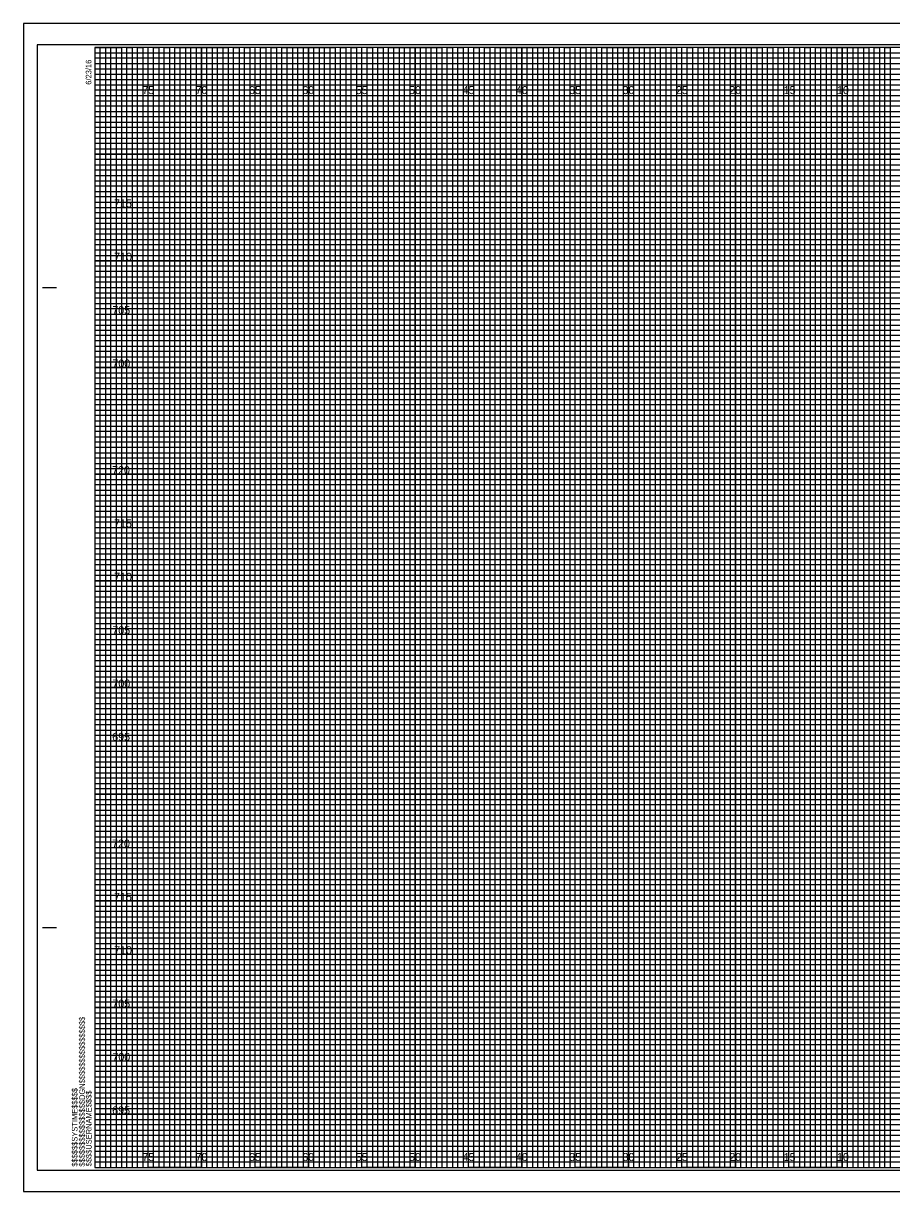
# Model space of a CAD drawing. Extents: x -7 to 162, y -2 to 107.
# Drawn here: x -6.7 to 74.6, y -2.2 to 107.2 of the extents above; entities that cross this region are included whole.
import ezdxf

# ---------------------------------------------------------------- set-up
doc = ezdxf.new("R2010")
doc.units = 0
for name, color, linetype in [('Exist Cross Section Cell', 7, 'Continuous'), ('Exist XS Center Line Elevation Label', 7, 'Continuous'), ('Exist XS Ground Line', 7, 'Continuous'), ('Prop CMT Pvmt Course 2', 7, 'Continuous'), ('Prop CMT Pvmt Course 3', 7, 'Continuous'), ('Prop CMT Pvmt Surface', 7, 'Continuous'), ('Prop CMT Pvmt Surface Shoulder', 7, 'Continuous'), ('Prop CMT Shld Paved Course 1', 7, 'Continuous'), ('Prop CMT Shld Paved Course 2', 7, 'Continuous'), ('Prop CMT Subgrade Earthwork', 7, 'Continuous'), ('Scratch_Level_7', 7, 'Continuous')]:
    doc.layers.add(name, color=color, linetype=linetype)

msp = doc.modelspace()

# ---------------------------------------------------------------- linework, layer by layer
at = {"layer": 'Exist XS Center Line Elevation Label'}
for points in [[(0, 105), (2.5, 105), (2.5, 0), (7.5, 0), (7.5, 105), (12.5, 105), (12.5, 0), (17.5, 0), (17.5, 105), (22.5, 105), (22.5, 0), (27.5, 0), (27.5, 105), (32.5, 105), (32.5, 0), (37.5, 0), (37.5, 105), (42.5, 105), (42.5, 0), (47.5, 0), (47.5, 105), (52.5, 105), (52.5, 0), (57.5, 0), (57.5, 105), (62.5, 105), (62.5, 0), (67.5, 0), (67.5, 105), (72.5, 105), (72.5, 0), (77.5, 0)], [(0, 102.5), (137.5, 102.5)], [(0, 92.5), (160, 92.5), (160, 97.5), (0, 97.5)], [(0, 82.5), (160, 82.5), (160, 87.5), (0, 87.5)], [(0, 72.5), (160, 72.5), (160, 77.5), (0, 77.5)], [(0, 62.5), (160, 62.5), (160, 67.5), (0, 67.5)], [(0, 52.5), (160, 52.5), (160, 57.5), (0, 57.5)], [(0, 42.5), (160, 42.5), (160, 47.5), (0, 47.5)], [(0, 32.5), (160, 32.5), (160, 37.5), (0, 37.5)], [(0, 22.5), (160, 22.5), (160, 27.5), (0, 27.5)], [(0, 12.5), (160, 12.5), (160, 17.5), (0, 17.5)], [(0, 2.5), (160, 2.5), (160, 7.5), (0, 7.5)]]:
    msp.add_lwpolyline(points, dxfattribs=at)
at = {"layer": 'Exist XS Ground Line'}
for p, q in [((5, 105), (0, 105)), ((5, 0), (5, 105)), ((15, 105), (10, 105)), ((10, 105), (10, 0)), ((15, 0), (15, 105)), ((25, 105), (20, 105)), ((20, 105), (20, 0)), ((25, 0), (25, 105)), ((35, 105), (30, 105)), ((30, 105), (30, 0)), ((35, 0), (35, 105)), ((45, 105), (40, 105)), ((40, 105), (40, 0)), ((45, 0), (45, 105)), ((55, 105), (50, 105)), ((50, 105), (50, 0)), ((55, 0), (55, 105)), ((65, 105), (60, 105)), ((60, 105), (60, 0)), ((65, 0), (65, 105)), ((75, 105), (70, 105)), ((70, 105), (70, 0)), ((10, 0), (5, 0)), ((20, 0), (15, 0)), ((30, 0), (25, 0)), ((40, 0), (35, 0)), ((50, 0), (45, 0)), ((60, 0), (55, 0)), ((70, 0), (65, 0))]:
    msp.add_line(p, q, dxfattribs=at)
for points in [[(0, 100), (160, 100), (160, 95), (0, 95)], [(0, 90), (160, 90), (160, 85), (0, 85)], [(0, 80), (160, 80), (160, 75), (0, 75)], [(0, 70), (160, 70), (160, 65), (0, 65)], [(0, 60), (160, 60), (160, 55), (0, 55)], [(0, 50), (160, 50), (160, 45), (0, 45)], [(0, 40), (160, 40), (160, 35), (0, 35)], [(0, 30), (160, 30), (160, 25), (0, 25)], [(0, 20), (160, 20), (160, 15), (0, 15)], [(0, 10), (160, 10), (160, 5), (0, 5)]]:
    msp.add_lwpolyline(points, dxfattribs=at)
at = {"layer": 'Prop CMT Pvmt Course 2'}
msp.add_lwpolyline([(-6.7, -2.25), (161.65, -2.25), (161.65, 107.25), (-6.7, 107.25)], close=True, dxfattribs=at)
at = {"layer": 'Prop CMT Pvmt Course 3'}
msp.add_lwpolyline([(-5.4, -0.25), (161.2, -0.25), (161.2, 105.25), (-5.4, 105.25)], close=True, dxfattribs=at)
at = {"layer": 'Prop CMT Pvmt Surface'}
for p, q in [((161.65, 107.25), (-6.7, 107.25)), ((-6.7, 107.25), (-6.7, -2.25)), ((-6.7, -2.25), (161.65, -2.25))]:
    msp.add_line(p, q, dxfattribs=at)
at = {"layer": 'Prop CMT Shld Paved Course 1'}
for p, q in [((-4.9, 82.5), (-3.65, 82.5)), ((-4.85, 82.5), (-3.6, 82.5)), ((-4.9, 22.5), (-3.65, 22.5)), ((-4.85, 22.5), (-3.6, 22.5)), ((0, 0), (0, 0)), ((0, 0), (0, 0)), ((0, 0), (0, 0)), ((0, 0), (0, 0)), ((0, 0), (0, 0)), ((0, 0), (0, 0)), ((0, 0), (0, 0))]:
    msp.add_line(p, q, dxfattribs=at)
msp.add_lwpolyline([(160, 105), (0, 105), (0, 0), (160, 0)], close=True, dxfattribs=at)
at = {"layer": 'Prop CMT Shld Paved Course 2'}
for points in [[(0, 0), (0.5, 0), (0.5, 105), (1, 105), (1, 0)], [(1, 0), (1.5, 0), (1.5, 105), (2, 105), (2, 0)], [(2.5, 0), (3, 0), (3, 105), (3.5, 105), (3.5, 0)], [(3.5, 0), (4, 0), (4, 105), (4.5, 105), (4.5, 0)], [(5, 0), (5.5, 0), (5.5, 105), (6, 105), (6, 0)], [(6, 0), (6.5, 0), (6.5, 105), (7, 105), (7, 0)], [(7.5, 0), (8, 0), (8, 105), (8.5, 105), (8.5, 0)], [(8.5, 0), (9, 0), (9, 105), (9.5, 105), (9.5, 0)], [(10, 0), (10.5, 0), (10.5, 105), (11, 105), (11, 0)], [(11, 0), (11.5, 0), (11.5, 105), (12, 105), (12, 0)], [(12.5, 0), (13, 0), (13, 105), (13.5, 105), (13.5, 0)], [(13.5, 0), (14, 0), (14, 105), (14.5, 105), (14.5, 0)], [(15, 0), (15.5, 0), (15.5, 105), (16, 105), (16, 0)], [(16, 0), (16.5, 0), (16.5, 105), (17, 105), (17, 0)], [(17.5, 0), (18, 0), (18, 105), (18.5, 105), (18.5, 0)], [(18.5, 0), (19, 0), (19, 105), (19.5, 105), (19.5, 0)], [(20, 0), (20.5, 0), (20.5, 105), (21, 105), (21, 0)], [(21, 0), (21.5, 0), (21.5, 105), (22, 105), (22, 0)], [(22.5, 0), (23, 0), (23, 105), (23.5, 105), (23.5, 0)], [(23.5, 0), (24, 0), (24, 105), (24.5, 105), (24.5, 0)], [(25, 0), (25.5, 0), (25.5, 105), (26, 105), (26, 0)], [(26, 0), (26.5, 0), (26.5, 105), (27, 105), (27, 0)], [(27.5, 0), (28, 0), (28, 105), (28.5, 105), (28.5, 0)], [(28.5, 0), (29, 0), (29, 105), (29.5, 105), (29.5, 0)], [(30, 0), (30.5, 0), (30.5, 105), (31, 105), (31, 0)], [(31, 0), (31.5, 0), (31.5, 105), (32, 105), (32, 0)], [(32.5, 0), (33, 0), (33, 105), (33.5, 105), (33.5, 0)], [(33.5, 0), (34, 0), (34, 105), (34.5, 105), (34.5, 0)], [(35, 0), (35.5, 0), (35.5, 105), (36, 105), (36, 0)], [(36, 0), (36.5, 0), (36.5, 105), (37, 105), (37, 0)], [(37.5, 0), (38, 0), (38, 105), (38.5, 105), (38.5, 0)], [(38.5, 0), (39, 0), (39, 105), (39.5, 105), (39.5, 0)], [(40, 0), (40.5, 0), (40.5, 105), (41, 105), (41, 0)], [(41, 0), (41.5, 0), (41.5, 105), (42, 105), (42, 0)], [(42.5, 0), (43, 0), (43, 105), (43.5, 105), (43.5, 0)], [(43.5, 0), (44, 0), (44, 105), (44.5, 105), (44.5, 0)], [(45, 0), (45.5, 0), (45.5, 105), (46, 105), (46, 0)], [(46, 0), (46.5, 0), (46.5, 105), (47, 105), (47, 0)], [(47.5, 0), (48, 0), (48, 105), (48.5, 105), (48.5, 0)], [(48.5, 0), (49, 0), (49, 105), (49.5, 105), (49.5, 0)], [(50, 0), (50.5, 0), (50.5, 105), (51, 105), (51, 0)], [(51, 0), (51.5, 0), (51.5, 105), (52, 105), (52, 0)], [(52.5, 0), (53, 0), (53, 105), (53.5, 105), (53.5, 0)], [(53.5, 0), (54, 0), (54, 105), (54.5, 105), (54.5, 0)], [(55, 0), (55.5, 0), (55.5, 105), (56, 105), (56, 0)], [(56, 0), (56.5, 0), (56.5, 105), (57, 105), (57, 0)], [(57.5, 0), (58, 0), (58, 105), (58.5, 105), (58.5, 0)], [(58.5, 0), (59, 0), (59, 105), (59.5, 105), (59.5, 0)], [(60, 0), (60.5, 0), (60.5, 105), (61, 105), (61, 0)], [(61, 0), (61.5, 0), (61.5, 105), (62, 105), (62, 0)], [(62.5, 0), (63, 0), (63, 105), (63.5, 105), (63.5, 0)], [(63.5, 0), (64, 0), (64, 105), (64.5, 105), (64.5, 0)], [(65, 0), (65.5, 0), (65.5, 105), (66, 105), (66, 0)], [(66, 0), (66.5, 0), (66.5, 105), (67, 105), (67, 0)], [(67.5, 0), (68, 0), (68, 105), (68.5, 105), (68.5, 0)], [(68.5, 0), (69, 0), (69, 105), (69.5, 105), (69.5, 0)], [(70, 0), (70.5, 0), (70.5, 105), (71, 105), (71, 0)], [(71, 0), (71.5, 0), (71.5, 105), (72, 105), (72, 0)], [(72.5, 0), (73, 0), (73, 105), (73.5, 105), (73.5, 0)], [(73.5, 0), (74, 0), (74, 105), (74.5, 105), (74.5, 0)]]:
    msp.add_lwpolyline(points, dxfattribs=at)
at = {"layer": 'Prop CMT Subgrade Earthwork'}
for p, q in [((5, 0), (5, 105)), ((10, 0), (10, 105)), ((15, 0), (15, 105)), ((20, 0), (20, 105)), ((25, 0), (25, 105)), ((30, 0), (30, 105)), ((35, 0), (35, 105)), ((40, 0), (40, 105)), ((45, 0), (45, 105)), ((50, 0), (50, 105)), ((55, 0), (55, 105)), ((60, 0), (60, 105)), ((65, 0), (65, 105)), ((70, 0), (70, 105)), ((0, 100), (160, 100)), ((0, 95), (160, 95)), ((0, 90), (160, 90)), ((0, 85), (160, 85)), ((0, 80), (160, 80)), ((0, 75), (160, 75)), ((0, 70), (160, 70)), ((0, 65), (160, 65)), ((0, 60), (160, 60)), ((0, 55), (160, 55)), ((0, 50), (160, 50)), ((0, 45), (160, 45)), ((0, 40), (160, 40)), ((0, 35), (160, 35)), ((0, 30), (160, 30)), ((0, 25), (160, 25)), ((0, 20), (160, 20)), ((0, 15), (160, 15)), ((0, 10), (160, 10)), ((0, 5), (160, 5))]:
    msp.add_line(p, q, dxfattribs=at)
at = {"layer": 'Scratch_Level_7'}
for p, q in [((0, 104.5), (130, 104.5)), ((130, 103.99), (0, 103.99)), ((0, 103.99), (0, 103.5)), ((0, 103.5), (130, 103.5)), ((130, 102.95), (0, 102.95)), ((0, 102.95), (0, 102)), ((0, 102), (160, 102))]:
    msp.add_line(p, q, dxfattribs=at)
for points in [[(0, 101.5), (135, 101.5), (160, 101.5), (160, 101), (0, 101)], [(0, 100.5), (160, 100.5), (160, 99.5), (0, 99.5)], [(0, 99), (160, 99), (160, 98.5), (0, 98.49)], [(0, 98), (160, 98), (160, 97), (0, 97)], [(0, 96.5), (160, 96.5), (160, 96), (0, 96)], [(0, 95.5), (160, 95.5), (160, 94.5), (0, 94.5)], [(0, 94), (160, 94), (160, 93.5), (0, 93.5)], [(0, 93), (160, 93), (160, 92), (0, 92)], [(0, 91.5), (160, 91.5), (160, 91), (0, 91)], [(0, 90.5), (160, 90.5), (160, 89.5), (0, 89.5)], [(0, 89), (160, 89), (160, 88.5), (0, 88.5)], [(0, 88), (160, 88), (160, 86.98), (160, 86.5), (160, 86), (0, 86)], [(0, 87), (160, 87), (160, 86.5), (0, 86.5)], [(0, 85.5), (160, 85.5), (160, 84.5), (0, 84.52)], [(0, 84.52), (160, 84.5), (160, 84), (0, 84)], [(0, 83.5), (160, 83.5), (160, 83), (0, 83)], [(0, 82), (160, 82), (160, 81.5), (0, 81.5)], [(0, 81), (160, 81), (160, 80.5), (0, 80.5)], [(-0.04, 79.45), (160, 79.45), (160, 78.94), (-0.04, 78.94)], [(0, 78.5), (160, 78.5), (160, 78), (0, 78)], [(0, 77), (160, 77), (160, 76.5), (0, 76.5)], [(0, 76), (160, 76), (160, 75.5), (0, 75.5)], [(0, 74.5), (160, 74.5), (160, 74), (0, 74)], [(0, 73.5), (160, 73.5), (160, 73), (0, 73)], [(0, 72), (160, 72), (160, 71.5), (0, 71.5)], [(0, 71), (160, 71), (160, 70.5), (0, 70.5)], [(0, 69.5), (160, 69.5), (160, 68.99), (0, 69)], [(0, 68.5), (160, 68.5), (160, 68), (0, 68)], [(0, 67), (160, 67), (160, 66.5), (0, 66.5)], [(0, 66), (160, 66), (160, 65.5), (0, 65.5)], [(0, 64.5), (160, 64.5), (160, 64), (0, 64)], [(0, 63.5), (160, 63.5), (160, 63), (0, 63)], [(0, 62), (160, 62), (160, 61.5), (0, 61.5)], [(0, 61), (160, 61), (160, 60.5), (0, 60.5)], [(0, 59.5), (160, 59.5), (160, 59), (0, 59)], [(0, 58.5), (160.03, 58.45), (160, 58), (0, 58)], [(0, 57), (160, 57), (160, 56.5), (0, 56.5)], [(0, 56), (160, 56), (160, 55.5), (0, 55.5)], [(0, 54.5), (160, 54.5), (160, 54), (0, 54)], [(0, 53.5), (160, 53.5), (160, 53), (0, 53)], [(0, 52), (160, 52), (160, 51.5), (0, 51.5)], [(0, 51), (160, 51), (160, 50.5), (0, 50.5)], [(0, 49.5), (160, 49.5), (160, 49), (0, 49)], [(0, 48.5), (160, 48.5), (160, 48), (0, 48)], [(0, 47), (160, 47), (160, 46.5), (0, 46.5)], [(0, 46), (160, 46), (160, 45.5), (0, 45.5)], [(0, 44.5), (160, 44.5), (160, 44), (0, 44)], [(0, 43.5), (160, 43.5), (160, 43), (0, 43)], [(0, 42), (160, 42), (160, 41.5), (0, 41.5)], [(0, 41), (160, 41), (160, 40.5), (0, 40.5)], [(0, 39.5), (160, 39.5), (160, 38.99), (0, 39)], [(0, 38.5), (160, 38.5), (160, 38), (0, 38)], [(0, 37), (160, 37), (160, 36.5), (0, 36.5)], [(0, 36), (160, 36), (160, 35.5), (0, 35.5)], [(0, 34.5), (160, 34.5), (160, 34), (0, 34)], [(0, 33.5), (160, 33.5), (160, 33), (0, 33)], [(0, 32), (160, 32), (160, 31.5), (0, 31.5)], [(0, 31), (160, 31), (160, 30.5), (0, 30.5)], [(0, 29.5), (160, 29.5), (160, 29), (0, 29)], [(0, 28.5), (160.03, 28.46), (160, 28), (0, 28)], [(0, 27), (160, 27), (160, 26.5), (0, 26.5)], [(0, 26), (160, 26), (160, 25.5), (0, 25.5)], [(0, 24.5), (160, 24.5), (160, 24), (0, 24)], [(0, 23.5), (160, 23.5), (160, 23), (0, 23)], [(0, 22), (160, 22), (160, 21.5), (0, 21.5)], [(0, 21), (160, 21), (160, 20.5), (0, 20.5)], [(0, 19.5), (160, 19.5), (160, 19), (0, 19)], [(0, 18.5), (160, 18.5), (160, 18), (0, 18)], [(0, 17), (160, 17), (160, 16.5), (0, 16.5)], [(0, 16), (160, 16), (160, 15.5), (0, 15.5)], [(0, 14.5), (160, 14.5), (160, 14), (0, 14)], [(0, 13.5), (160, 13.5), (160, 13), (0, 13)], [(0, 12), (160, 12), (160, 11.5), (0, 11.5)], [(0, 11), (160, 11), (160, 10.5), (0, 10.5)], [(0, 9.5), (160, 9.5), (160, 9), (0, 9)], [(0, 8.5), (160, 8.5), (160, 8), (0, 8)], [(0, 7), (160, 7), (160, 6.5), (0, 6.5)], [(0, 6), (160, 6), (160, 5.5), (0, 5.5)], [(0, 4.5), (160, 4.5), (160, 4), (0, 4)], [(0, 3.5), (160, 3.5), (160, 3), (0, 3)], [(0, 2), (160, 2), (160, 1.5), (0, 1.5)], [(0, 1), (160, 1), (160, 0.5), (0, 0.5)]]:
    msp.add_lwpolyline(points, dxfattribs=at)

# ---------------------------------------------------------------- texts
at = {"layer": 'Exist Cross Section Cell'}
for s, p in [('75', (4.44, 100.62)), ('70', (9.43, 100.62)), ('65', (14.44, 100.62)), ('60', (19.43, 100.62)), ('55', (24.44, 100.62)), ('50', (29.43, 100.62)), ('45', (34.44, 100.62)), ('40', (39.43, 100.62)), ('35', (44.44, 100.62)), ('30', (49.43, 100.62)), ('25', (54.44, 100.62)), ('20', (59.43, 100.62)), ('15', (64.53, 100.62)), ('10', (69.52, 100.62)), ('75', (4.44, 0.62)), ('70', (9.43, 0.62)), ('65', (14.44, 0.62)), ('60', (19.43, 0.62)), ('55', (24.44, 0.62)), ('50', (29.43, 0.62)), ('45', (34.44, 0.62)), ('40', (39.43, 0.62)), ('35', (44.44, 0.62)), ('30', (49.43, 0.62)), ('25', (54.44, 0.62)), ('20', (59.43, 0.62)), ('15', (64.53, 0.62)), ('10', (69.52, 0.62))]:
    msp.add_text(s, height=0.75, dxfattribs=at).set_placement(p)
at = {"layer": 'Prop CMT Pvmt Surface Shoulder'}
for s, p in [('715', (1.79, 90)), ('710', (1.8, 85)), ('705', (1.63, 80)), ('700', (1.64, 75)), ('720', (1.61, 65)), ('715', (1.79, 60)), ('710', (1.8, 55)), ('705', (1.63, 50)), ('700', (1.64, 45)), ('695', (1.62, 40)), ('720', (1.61, 30)), ('715', (1.79, 25)), ('710', (1.8, 20)), ('705', (1.63, 15)), ('700', (1.64, 10)), ('695', (1.62, 5))]:
    msp.add_text(s, height=0.75, dxfattribs=at).set_placement(p)
at = {"layer": 'Prop CMT Shld Paved Course 1'}
for s, p in [('6/23/16', (-0.33, 101.5)), ('$$$$$$$$$$$$$$$$DGN$$$$$$$$$$$$$$$$', (-0.94, 0.09)), ('$$$$$$SYSTIME$$$$$', (-1.63, 0.09)), ('$$$$USERNAME$$$$', (-0.31, 0.12))]:
    msp.add_text(s, height=0.525, rotation=90, dxfattribs=at).set_placement(p)

doc.saveas('drawing.dxf')
